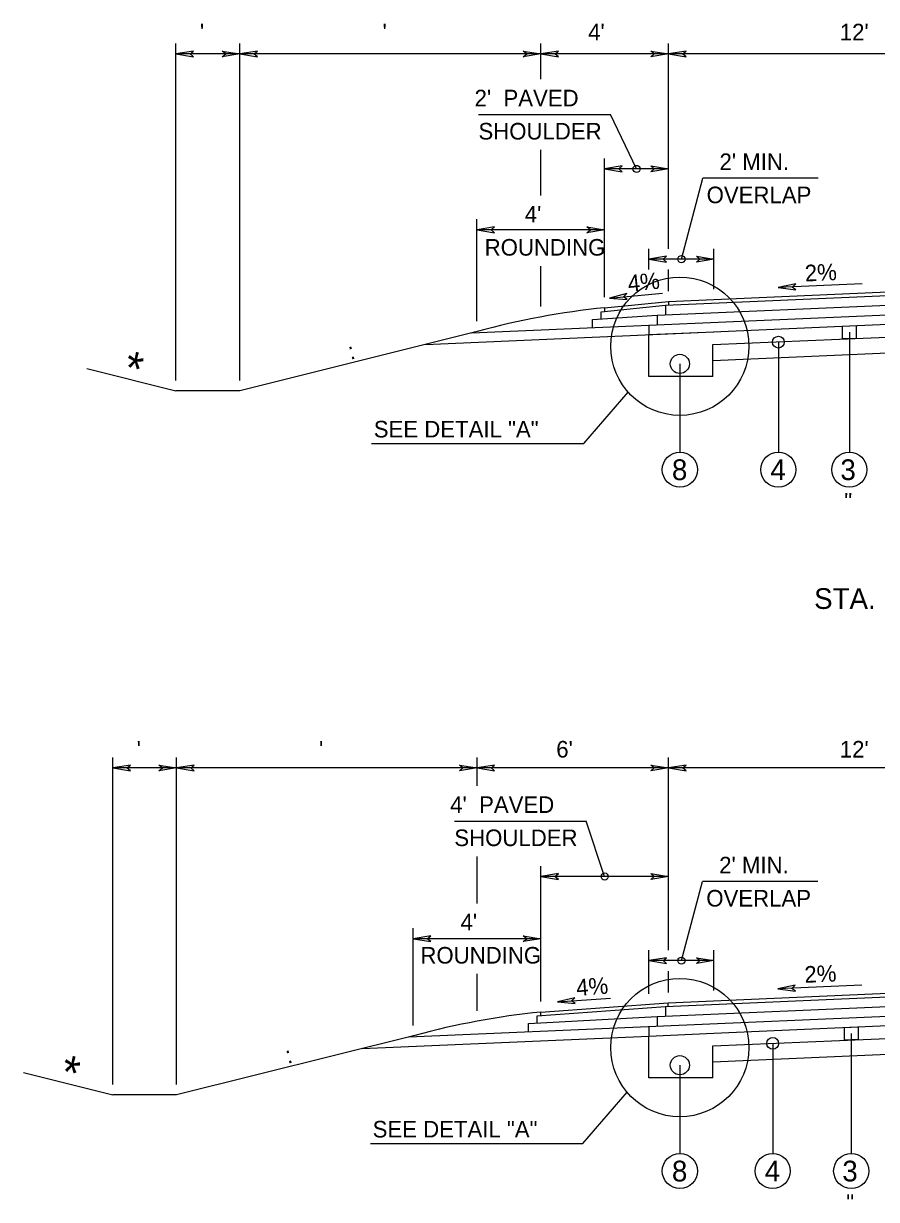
# Model space of a CAD drawing. Extents: x -592 to 1199, y -590 to 416.
# Drawn here: x 155.3 to 227.3, y 170.1 to 269.4 of the extents above; entities that cross this region are included whole.
import ezdxf

# ---------------------------------------------------------------- set-up
doc = ezdxf.new("R2010")
doc.units = 0
doc.layers.add('1', color=7, linetype='Continuous')
doc.layers.add('Des_ Drain_ Ftrs', color=7, linetype='Continuous')

msp = doc.modelspace()

# ---------------------------------------------------------------- linework, layer by layer
at = {"layer": '1'}
for p, q in [((168.174, 239.248), (168.174, 267.693)), ((173.563, 239.248), (173.563, 267.693)), ((198.981, 264.7), (198.981, 267.693)), ((209.758, 250.367), (209.758, 267.693)), ((173.563, 266.813), (168.174, 266.813)), ((198.981, 266.813), (173.563, 266.813)), ((209.758, 266.813), (198.981, 266.813)), ((242.087, 266.813), (209.758, 266.813)), ((193.716, 261.692), (204.857, 261.692)), ((207.064, 257.11), (204.857, 261.692)), ((198.976, 254.87), (198.976, 258.709)), ((204.37, 246.265), (204.37, 257.99)), ((209.758, 257.11), (204.37, 257.11)), ((210.859, 249.487), (212.649, 256.314)), ((222.413, 256.314), (212.649, 256.314)), ((193.588, 244.255), (193.588, 252.851)), ((204.37, 251.971), (193.593, 251.971)), ((208.116, 248.607), (208.116, 250.367)), ((213.602, 246.958), (213.602, 250.367)), ((213.602, 249.487), (208.116, 249.487)), ((198.976, 245.487), (198.976, 248.897)), ((209.758, 246.79), (209.758, 248.607)), ((209.752, 245.91), (242.087, 247.322)), ((226.112, 247.394), (219.027, 247.084)), ((204.777, 246.186), (209.254, 246.623)), ((209.518, 245.601), (242.087, 247.023)), ((193.166, 243.269), (242.087, 245.405)), ((204.065, 245.054), (209.518, 245.601)), ((204.37, 245.385), (209.752, 245.91)), ((204.37, 245.385), (204.37, 245.085)), ((208.815, 244.762), (242.087, 246.214)), ((209.518, 245.601), (209.518, 244.793)), ((209.753, 245.91), (209.753, 245.61)), ((189.245, 242.289), (242.087, 244.596)), ((203.338, 244.397), (208.815, 244.762)), ((203.338, 243.713), (203.338, 244.397)), ((204.065, 244.441), (204.065, 245.054)), ((208.815, 244.762), (208.815, 243.953)), ((193.593, 243.376), (173.563, 238.368)), ((208.111, 243.922), (208.111, 243.113)), ((208.111, 243.113), (213.597, 243.352)), ((213.499, 242.269), (242.087, 243.517)), ((225.035, 243.311), (225.035, 233.194)), ((208.111, 239.574), (208.111, 243.113)), ((219.041, 242.482), (219.041, 233.194)), ((213.499, 239.574), (213.499, 242.269)), ((213.499, 240.921), (242.087, 242.169)), ((210.725, 240.645), (210.725, 233.194)), ((160.639, 240.251), (168.174, 238.368)), ((213.499, 239.574), (208.111, 239.574)), ((173.563, 238.368), (168.174, 238.368)), ((202.621, 233.931), (206.361, 238.25)), ((184.69, 233.931), (202.621, 233.931)), ((162.834, 179.795), (162.834, 207.406)), ((168.222, 179.795), (168.222, 207.406)), ((193.593, 205.027), (193.593, 207.406)), ((209.758, 191.138), (209.758, 207.406)), ((168.222, 206.526), (162.834, 206.526)), ((193.593, 206.526), (168.222, 206.526)), ((209.758, 206.526), (193.593, 206.526)), ((242.087, 206.526), (209.758, 206.526)), ((191.679, 202.027), (202.82, 202.027)), ((204.37, 197.356), (202.82, 202.027)), ((193.593, 195.085), (193.593, 199.058)), ((198.981, 186.796), (198.981, 198.236)), ((209.758, 197.356), (198.981, 197.356)), ((210.859, 190.258), (212.621, 196.924)), ((222.385, 196.924), (212.621, 196.924)), ((188.204, 184.789), (188.204, 192.989)), ((198.981, 192.109), (188.205, 192.109)), ((208.116, 187.452), (208.116, 191.138)), ((213.602, 187.738), (213.602, 191.138)), ((213.602, 190.258), (208.116, 190.258)), ((193.593, 186.019), (193.593, 189.128)), ((209.758, 187.57), (209.758, 189.378)), ((209.518, 186.381), (242.087, 187.803)), ((209.749, 186.69), (242.087, 188.103)), ((226.08, 188.172), (218.994, 187.862)), ((198.983, 185.916), (209.749, 186.69)), ((200.387, 186.77), (204.874, 187.092)), ((208.811, 185.541), (242.087, 186.994)), ((209.749, 186.389), (209.749, 186.69)), ((187.828, 183.815), (242.087, 186.184)), ((198.678, 185.594), (209.518, 186.381)), ((198.983, 185.616), (198.983, 185.916)), ((209.518, 186.381), (209.518, 185.566)), ((197.951, 184.942), (208.811, 185.541)), ((197.951, 184.257), (197.951, 184.942)), ((198.678, 184.982), (198.678, 185.594)), ((208.111, 184.699), (208.111, 183.892)), ((208.811, 185.541), (208.811, 184.726)), ((213.597, 184.131), (242.087, 185.375)), ((188.333, 183.941), (168.222, 178.915)), ((183.905, 182.835), (208.111, 183.892)), ((208.111, 183.892), (213.597, 184.132)), ((208.111, 180.354), (208.111, 183.892)), ((213.499, 183.048), (242.087, 184.297)), ((225.195, 184.098), (225.195, 173.973)), ((213.499, 181.7), (242.087, 182.949)), ((213.5, 180.354), (213.5, 183.048)), ((218.565, 183.27), (218.565, 173.973)), ((155.298, 180.799), (162.834, 178.915)), ((210.725, 181.425), (210.725, 173.973)), ((213.5, 180.354), (208.111, 180.354)), ((168.222, 178.915), (162.834, 178.915)), ((202.526, 174.82), (206.266, 179.14)), ((184.594, 174.82), (202.526, 174.82))]:
    msp.add_line(p, q, dxfattribs=at)
for points in [[(224.461, 243.827), (225.608, 243.877), (225.608, 242.798), (224.461, 242.748)], [(224.622, 184.613), (225.768, 184.663), (225.768, 183.584), (224.622, 183.534)]]:
    msp.add_lwpolyline(points, close=True, dxfattribs=at)
for centre, radius in [((207.064, 257.11), 0.3), ((210.859, 249.487), 0.3), ((210.723, 242.133), 5.838), ((219.041, 242.482), 0.5), ((210.725, 240.645), 0.808), ((210.725, 231.708), 1.485), ((219.041, 231.708), 1.485), ((225.035, 231.708), 1.485), ((204.37, 197.356), 0.3), ((210.859, 190.258), 0.3), ((210.723, 182.912), 5.838), ((218.565, 183.269), 0.5), ((210.725, 181.425), 0.808), ((210.725, 172.488), 1.485), ((218.565, 172.488), 1.485), ((225.195, 172.488), 1.485)]:
    msp.add_circle(centre, radius, dxfattribs=at)
for centre, end in [((211.252, 178.551), 105.23809), ((205.865, 119.082), 105.12625)]:
    msp.add_arc(centre, 67.188, 95.87953, end, dxfattribs=at)
at = {"layer": 'Des_ Drain_ Ftrs'}
for points in [[(168.174, 266.813), (169.663, 266.565), (169.368, 266.813), (169.663, 267.062)], [(173.563, 266.813), (172.074, 266.565), (172.369, 266.813), (172.074, 267.062)], [(173.563, 266.813), (175.051, 266.565), (174.756, 266.813), (175.051, 267.062)], [(198.981, 266.813), (197.493, 266.565), (197.788, 266.813), (197.493, 267.062)], [(198.981, 266.813), (200.47, 266.565), (200.175, 266.813), (200.47, 267.062)], [(209.758, 266.813), (208.27, 266.565), (208.565, 266.813), (208.27, 267.062)], [(209.758, 266.813), (211.246, 266.565), (210.951, 266.813), (211.246, 267.062)], [(204.37, 257.11), (205.858, 256.861), (205.563, 257.11), (205.858, 257.358)], [(209.758, 257.11), (208.27, 256.861), (208.565, 257.11), (208.27, 257.358)], [(193.593, 251.971), (195.081, 251.723), (194.786, 251.971), (195.081, 252.22)], [(204.37, 251.971), (202.881, 251.723), (203.176, 251.971), (202.881, 252.22)], [(208.116, 249.487), (209.604, 249.239), (209.309, 249.487), (209.604, 249.735)], [(213.602, 249.487), (212.114, 249.239), (212.409, 249.487), (212.114, 249.735)], [(219.027, 247.084), (220.524, 246.901), (220.219, 247.136), (220.503, 247.397)], [(204.777, 246.186), (206.282, 246.082), (205.965, 246.301), (206.234, 246.577)], [(162.834, 206.526), (164.322, 206.278), (164.027, 206.526), (164.322, 206.774)], [(168.222, 206.526), (166.734, 206.278), (167.029, 206.526), (166.734, 206.774)], [(168.222, 206.526), (169.71, 206.278), (169.415, 206.526), (169.71, 206.774)], [(193.593, 206.526), (192.105, 206.278), (192.4, 206.526), (192.105, 206.774)], [(193.593, 206.526), (195.081, 206.278), (194.786, 206.526), (195.081, 206.774)], [(209.758, 206.526), (208.27, 206.278), (208.565, 206.526), (208.27, 206.774)], [(209.758, 206.526), (211.246, 206.278), (210.951, 206.526), (211.246, 206.774)], [(198.981, 197.356), (200.47, 197.107), (200.175, 197.356), (200.47, 197.604)], [(209.758, 197.356), (208.27, 197.107), (208.565, 197.356), (208.27, 197.604)], [(188.205, 192.109), (189.693, 191.861), (189.398, 192.109), (189.693, 192.357)], [(198.981, 192.109), (197.493, 191.861), (197.788, 192.109), (197.493, 192.357)], [(208.116, 190.258), (209.604, 190.01), (209.309, 190.258), (209.604, 190.506)], [(213.602, 190.258), (212.114, 190.01), (212.409, 190.258), (212.114, 190.506)], [(218.994, 187.862), (220.492, 187.679), (220.187, 187.914), (220.47, 188.175)], [(200.387, 186.77), (201.889, 186.628), (201.578, 186.854), (201.854, 187.123)]]:
    msp.add_lwpolyline(points, close=True, dxfattribs=at)

# ---------------------------------------------------------------- texts
at = {"layer": '1'}
for s, height, p in [(" '", 1.4, (169.673, 267.964)), ("  '", 1.4, (184.576, 267.964)), ("4'", 1.4, (202.979, 267.964)), ("12'", 1.4, (224.229, 267.964)), ("2'  PAVED", 1.4, (193.389, 262.392)), ('SHOULDER', 1.4, (193.715, 259.592)), ("2' MIN.", 1.4, (214.073, 257.014)), ('OVERLAP', 1.4, (212.984, 254.214)), ("4'", 1.4, (197.629, 252.587)), ('ROUNDING', 1.4, (194.24, 249.787)), ('SEE DETAIL "A"', 1.4, (184.875, 234.434)), ('8', 1.75, (210.052, 230.833)), ('4', 1.75, (218.366, 230.833)), ('3', 1.75, (224.279, 230.833)), (' "', 1.4, (224.091, 228.349)), ('STA.    +      TO STA.    +     ', 1.75, (222.058, 219.954)), (" '", 1.4, (164.333, 207.407)), ("  '", 1.4, (179.212, 207.407)), ("6'", 1.4, (200.285, 207.407)), ("12'", 1.4, (224.229, 207.407)), ("4'  PAVED", 1.4, (191.329, 202.727)), ('SHOULDER', 1.4, (191.678, 199.927)), ("2' MIN.", 1.4, (214.045, 197.624)), ('OVERLAP', 1.4, (212.956, 194.824)), ("4'", 1.4, (192.203, 192.809)), ('ROUNDING', 1.4, (188.814, 190.009)), ('SEE DETAIL "A"', 1.4, (184.779, 175.324)), ('8', 1.75, (210.052, 171.613)), ('4', 1.75, (217.89, 171.613)), ('3', 1.75, (224.439, 171.613)), (' "', 1.4, (224.251, 169.128))]:
    msp.add_text(s, height=height, dxfattribs=at).set_placement(p)
for s, height, rotation, p in [('4%', 1.4, 5.85556, (206.391, 246.729)), ('2%', 1.4, 2.62347, (221.303, 247.599)), ('*', 2.8, 347.15207, (163.581, 239.064)), (' : ', 1.4, 14.22821, (182.398, 240.859)), ('2%', 1.4, 2.62627, (221.271, 188.376)), ('4%', 1.4, 4.39312, (202.015, 187.271)), ('*', 2.8, 347.15207, (158.24, 179.612)), (' : ', 1.4, 14.22821, (177.098, 181.415))]:
    msp.add_text(s, height=height, rotation=rotation, dxfattribs=at).set_placement(p)

doc.saveas('drawing.dxf')
